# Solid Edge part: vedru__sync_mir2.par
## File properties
Author: KULL
Template: Iso Metric Part.par
Last saved by: KULL
Revision: 2
Application: Solid Edge
Accuracy: 0,990
Username: KULL
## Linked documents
vedru__sync.par
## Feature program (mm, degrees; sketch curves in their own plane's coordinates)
part copy "CopiedPart_1"
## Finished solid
Body 1: solid body, 3 faces, 4 edges, 4 vertices.
  Faces by surface: torus 2, spline 1
  Edges by curve: circle 2, intersection 2
Bounding box of the edges (mm; curved faces can reach further): 6.787 x 25.640 x 26.544, from (-6.7872, -79.3784, 14.3974) to (0, -53.7383, 40.9412).
Toroidal faces (ring radius, tube radius in mm): R5.8516 r1.2 x2
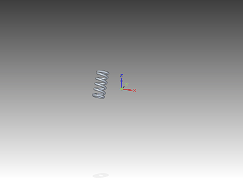
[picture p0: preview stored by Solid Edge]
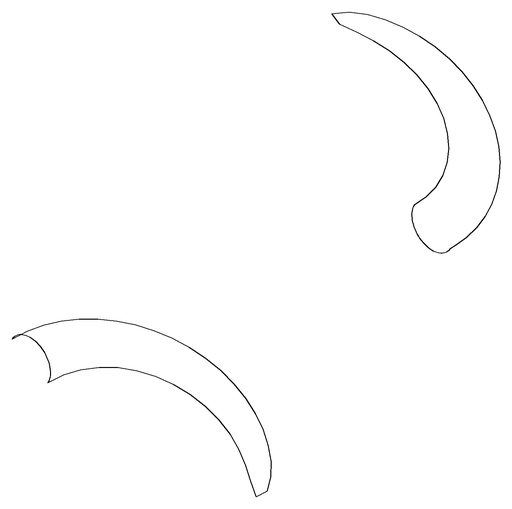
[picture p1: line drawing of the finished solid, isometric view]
